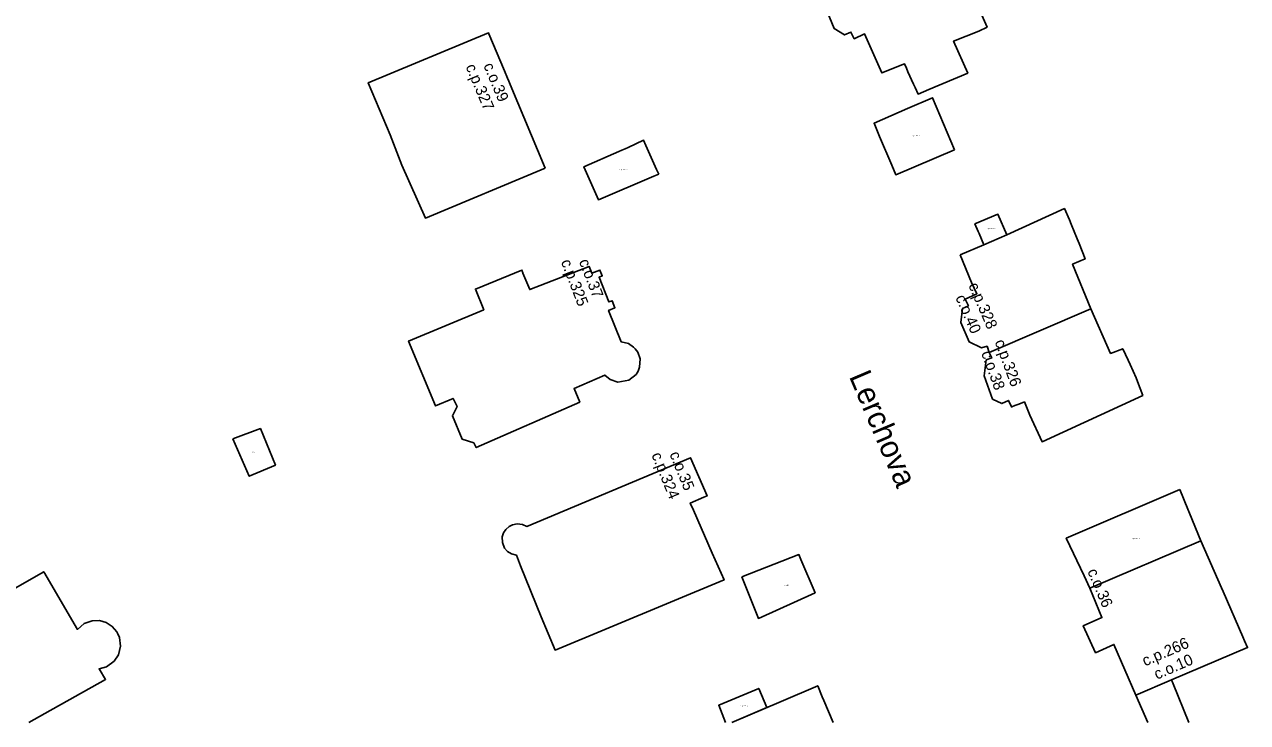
# Model space of a CAD drawing. Extents: x -600391 to -599491, y -1160176 to -1159402.
# Drawn here: x -599964.8 to -599855.4, y -1160176.1 to -1160113.6 of the extents above; entities that cross this region are included whole.
import ezdxf

# ---------------------------------------------------------------- set-up
doc = ezdxf.new("R2010")
doc.units = 0
for name, color, linetype in [('Level 10', 7, 'Continuous'), ('Level 11', 7, 'Continuous'), ('Level 12', 7, 'Continuous'), ('Level 24', 7, 'Continuous'), ('Level 25', 7, 'Continuous'), ('Level 61', 7, 'Continuous'), ('Level 62', 7, 'Continuous')]:
    doc.layers.add(name, color=color, linetype=linetype)

msp = doc.modelspace()

# ---------------------------------------------------------------- linework, layer by layer
at = {"layer": 'Level 61'}
for p, q in [((-599864.34, -1160176.08), (-599865.41, -1160173.62)), ((-599862.05, -1160172.61), (-599860.65, -1160176.08)), ((-599902.11, -1160176.08), (-599902.72, -1160174.53)), ((-599901.54, -1160176.08), (-599897.15, -1160174.19)), ((-599898.42, -1160174.74), (-599901.54, -1160176.08)), ((-599893.32, -1160174.09), (-599892.5, -1160176.08)), ((-599963.01, -1160175.26), (-599964.44, -1160176.08))]:
    msp.add_line(p, q, dxfattribs=at)
for points in [[(-599892.41, -1160113.94), (-599893.3, -1160111.75)], [(-599879.43, -1160112.2), (-599878.72, -1160113.81)], [(-599934.08, -1160118.79), (-599923.33, -1160114.31)], [(-599923.33, -1160114.31), (-599923.29, -1160114.41)], [(-599923.29, -1160114.41), (-599921.9, -1160117.72)], [(-599891.46, -1160114.5), (-599892.41, -1160113.94)], [(-599890.89, -1160114.25), (-599891.46, -1160114.5)], [(-599890.6, -1160114.85), (-599890.89, -1160114.25)], [(-599889.67, -1160114.41), (-599890.6, -1160114.85)], [(-599888.13, -1160117.9), (-599889.67, -1160114.41)], [(-599879.44, -1160114.17), (-599881.71, -1160115.05)], [(-599878.72, -1160113.81), (-599879.44, -1160114.17)], [(-599881.71, -1160115.05), (-599880.45, -1160117.92)], [(-599921.9, -1160117.72), (-599921.62, -1160118.39)], [(-599886.11, -1160117.08), (-599888.13, -1160117.9)], [(-599885.93, -1160117.49), (-599886.11, -1160117.08)], [(-599885.79, -1160117.81), (-599885.93, -1160117.49)], [(-599885.29, -1160118.9), (-599885.79, -1160117.81)], [(-599932.13, -1160123.44), (-599934.08, -1160118.79)], [(-599921.62, -1160118.39), (-599921.51, -1160118.66)], [(-599921.51, -1160118.66), (-599921.39, -1160118.94)], [(-599921.39, -1160118.94), (-599918.26, -1160126.43)], [(-599885.15, -1160119.22), (-599885.29, -1160118.9)], [(-599880.45, -1160117.92), (-599883.92, -1160119.39)], [(-599884.89, -1160119.8), (-599885.15, -1160119.22)], [(-599883.92, -1160119.39), (-599884.89, -1160119.8)], [(-599888.83, -1160122.41), (-599885.82, -1160121.1)], [(-599885.82, -1160121.1), (-599883.59, -1160120.13)], [(-599883.59, -1160120.13), (-599881.62, -1160124.79)], [(-599888.33, -1160123.61), (-599888.83, -1160122.41)], [(-599931.07, -1160126.16), (-599932.13, -1160123.44)], [(-599910.84, -1160124.59), (-599909.45, -1160123.93)], [(-599909.45, -1160123.93), (-599909.24, -1160124.4)], [(-599909.24, -1160124.4), (-599908.29, -1160126.56)], [(-599887.25, -1160126.17), (-599888.33, -1160123.61)], [(-599914.79, -1160126.31), (-599911.66, -1160124.94)], [(-599911.66, -1160124.94), (-599911.39, -1160124.82)], [(-599911.39, -1160124.82), (-599911.11, -1160124.71)], [(-599911.11, -1160124.71), (-599910.84, -1160124.59)], [(-599881.62, -1160124.79), (-599886.89, -1160127.03)], [(-599928.97, -1160130.9), (-599931.07, -1160126.16)], [(-599918.26, -1160126.43), (-599928.97, -1160130.9)], [(-599913.49, -1160129.26), (-599914.79, -1160126.31)], [(-599908.29, -1160126.56), (-599908.09, -1160126.97)], [(-599886.89, -1160127.03), (-599887.25, -1160126.17)], [(-599908.54, -1160127.16), (-599913.49, -1160129.26)], [(-599908.09, -1160126.97), (-599908.54, -1160127.16)], [(-599879.8, -1160131.43), (-599877.74, -1160130.56)], [(-599877.74, -1160130.56), (-599876.95, -1160132.42)], [(-599876.95, -1160132.42), (-599871.8, -1160130.05)], [(-599871.8, -1160130.05), (-599871.35, -1160131.07)], [(-599879.51, -1160132.11), (-599879.8, -1160131.43)], [(-599871.35, -1160131.07), (-599871.2, -1160131.45)], [(-599871.2, -1160131.45), (-599870.65, -1160132.77)], [(-599879.43, -1160132.3), (-599879.51, -1160132.11)], [(-599879.01, -1160133.3), (-599879.43, -1160132.3)], [(-599879.01, -1160133.3), (-599876.95, -1160132.42)], [(-599876.95, -1160132.42), (-599879.01, -1160133.3)], [(-599870.65, -1160132.77), (-599870.46, -1160133.19)], [(-599881.13, -1160134.21), (-599879.01, -1160133.3)], [(-599880.11, -1160136.67), (-599881.13, -1160134.21)], [(-599870.46, -1160133.19), (-599869.94, -1160134.56)], [(-599919.64, -1160137.31), (-599914.33, -1160135.23)], [(-599914.33, -1160135.23), (-599914.09, -1160135.85)], [(-599869.94, -1160134.56), (-599871.06, -1160135.04)], [(-599871.06, -1160135.04), (-599869.44, -1160139.03)], [(-599924.49, -1160137.27), (-599920.33, -1160135.56)], [(-599920.33, -1160135.56), (-599920.24, -1160135.82)], [(-599920.24, -1160135.82), (-599920.24, -1160135.83)], [(-599920.24, -1160135.83), (-599919.64, -1160137.31)], [(-599914.09, -1160135.85), (-599913.36, -1160135.56)], [(-599913.15, -1160136.09), (-599913.43, -1160136.21)], [(-599913.43, -1160136.21), (-599912.55, -1160138.42)], [(-599913.36, -1160135.56), (-599913.22, -1160135.92)], [(-599913.22, -1160135.92), (-599913.15, -1160136.09)], [(-599923.75, -1160139.12), (-599924.49, -1160137.27)], [(-599879.62, -1160137.68), (-599880.11, -1160136.67)], [(-599912.55, -1160138.42), (-599912.27, -1160138.31)], [(-599912.27, -1160138.31), (-599912.02, -1160138.94)], [(-599880.68, -1160138.16), (-599879.62, -1160137.68)], [(-599880.38, -1160138.76), (-599880.68, -1160138.16)], [(-599930.48, -1160141.92), (-599923.75, -1160139.12)], [(-599912.02, -1160138.94), (-599912.58, -1160139.17)], [(-599912.58, -1160139.17), (-599911.44, -1160141.99)], [(-599881.07, -1160140.26), (-599880.91, -1160139)], [(-599880.91, -1160139), (-599880.38, -1160138.76)], [(-599869.44, -1160139.03), (-599878.52, -1160142.95)], [(-599878.52, -1160142.95), (-599869.44, -1160139.03)], [(-599869.44, -1160139.03), (-599867.67, -1160143.03)], [(-599880.31, -1160141.99), (-599881.07, -1160140.26)], [(-599928.07, -1160147.73), (-599930.48, -1160141.92)], [(-599911.44, -1160141.99), (-599910.81, -1160142.14)], [(-599910.81, -1160142.14), (-599910.34, -1160142.45)], [(-599910.34, -1160142.45), (-599910.21, -1160142.61)], [(-599910.21, -1160142.61), (-599909.97, -1160142.91)], [(-599909.97, -1160142.91), (-599909.76, -1160143.5)], [(-599879.22, -1160142.53), (-599880.31, -1160141.99)], [(-599878.72, -1160142.38), (-599879.22, -1160142.53)], [(-599878.52, -1160142.95), (-599878.72, -1160142.38)], [(-599878.29, -1160143.42), (-599878.52, -1160142.95)], [(-599867.67, -1160143.03), (-599866.57, -1160142.6)], [(-599866.57, -1160142.6), (-599866.1, -1160143.63)], [(-599909.76, -1160143.5), (-599909.8, -1160144.26)], [(-599878.98, -1160145.04), (-599878.79, -1160143.6)], [(-599878.79, -1160143.6), (-599878.29, -1160143.42)], [(-599866.1, -1160143.63), (-599865.91, -1160144.02)], [(-599865.91, -1160144.02), (-599865.37, -1160145.2)], [(-599912.92, -1160144.97), (-599915.67, -1160146.16)], [(-599912.44, -1160145.37), (-599912.92, -1160144.97)], [(-599910.11, -1160144.9), (-599910.78, -1160145.43)], [(-599909.93, -1160144.6), (-599910.11, -1160144.9)], [(-599909.8, -1160144.26), (-599909.93, -1160144.6)], [(-599878.22, -1160147.11), (-599878.98, -1160145.04)], [(-599865.37, -1160145.2), (-599865.26, -1160145.55)], [(-599915.67, -1160146.16), (-599915.16, -1160147.38)], [(-599911.75, -1160145.59), (-599912.44, -1160145.37)], [(-599910.78, -1160145.43), (-599911.75, -1160145.59)], [(-599865.26, -1160145.55), (-599864.78, -1160146.78)], [(-599926.5, -1160147.06), (-599928.07, -1160147.73)], [(-599926.14, -1160147.79), (-599926.5, -1160147.06)], [(-599915.16, -1160147.38), (-599924.42, -1160151.46)], [(-599877.4, -1160147.51), (-599878.22, -1160147.11)], [(-599876.81, -1160147.23), (-599877.4, -1160147.51)], [(-599876.55, -1160147.76), (-599876.81, -1160147.23)], [(-599875.38, -1160147.37), (-599875.71, -1160147.5)], [(-599874.88, -1160148.56), (-599875.38, -1160147.37)], [(-599864.78, -1160146.78), (-599873.8, -1160150.94)], [(-599926.55, -1160148.61), (-599926.14, -1160147.79)], [(-599876.53, -1160147.81), (-599876.55, -1160147.76)], [(-599876.5, -1160147.8), (-599876.53, -1160147.81)], [(-599876.23, -1160147.7), (-599876.5, -1160147.8)], [(-599875.97, -1160147.6), (-599876.23, -1160147.7)], [(-599875.71, -1160147.5), (-599875.97, -1160147.6)], [(-599925.69, -1160150.71), (-599926.55, -1160148.61)], [(-599873.8, -1160150.94), (-599874.88, -1160148.56)], [(-599946.2, -1160150.66), (-599943.73, -1160149.75)], [(-599944.73, -1160154.03), (-599946.2, -1160150.66)], [(-599943.73, -1160149.75), (-599942.39, -1160153.02)], [(-599924.65, -1160151.02), (-599925.69, -1160150.71)], [(-599924.42, -1160151.46), (-599924.65, -1160151.02)], [(-599919.9, -1160158.52), (-599905.24, -1160152.37)], [(-599905.24, -1160152.37), (-599903.77, -1160155.79)], [(-599942.39, -1160153.02), (-599944.73, -1160154.03)], [(-599904.06, -1160155.91), (-599905.27, -1160156.43)], [(-599903.77, -1160155.79), (-599904.06, -1160155.91)], [(-599871.43, -1160159.47), (-599861.48, -1160155.2)], [(-599861.48, -1160155.2), (-599860.76, -1160156.96)], [(-599905.27, -1160156.43), (-599904.99, -1160157.06)], [(-599904.99, -1160157.06), (-599903.3, -1160160.9)], [(-599860.76, -1160156.96), (-599860.61, -1160157.32)], [(-599921.17, -1160158.36), (-599920.75, -1160158.28)], [(-599920.75, -1160158.28), (-599920.28, -1160158.33)], [(-599920.28, -1160158.33), (-599919.9, -1160158.52)], [(-599860.61, -1160157.32), (-599859.59, -1160159.8)], [(-599922.09, -1160159.45), (-599921.97, -1160159.09)], [(-599922.08, -1160159.95), (-599922.09, -1160159.45)], [(-599921.97, -1160159.09), (-599921.77, -1160158.78)], [(-599921.77, -1160158.78), (-599921.48, -1160158.51)], [(-599921.48, -1160158.51), (-599921.17, -1160158.36)], [(-599921.88, -1160160.45), (-599922.08, -1160159.95)], [(-599921.61, -1160160.75), (-599921.88, -1160160.45)], [(-599871.63, -1160159.57), (-599871.43, -1160159.47)], [(-599870.03, -1160162.95), (-599871.63, -1160159.57)], [(-599869.51, -1160164.05), (-599859.59, -1160159.8)], [(-599859.59, -1160159.8), (-599869.51, -1160164.05)], [(-599859.59, -1160159.8), (-599857.74, -1160164.02)], [(-599921.26, -1160160.97), (-599921.61, -1160160.75)], [(-599920.83, -1160161.09), (-599921.26, -1160160.97)], [(-599920.46, -1160162.04), (-599920.83, -1160161.09)], [(-599903.3, -1160160.9), (-599902.24, -1160163.3)], [(-599900.66, -1160163.02), (-599895.55, -1160161.04)], [(-599895.55, -1160161.04), (-599895.37, -1160161.48)], [(-599895.37, -1160161.48), (-599894.11, -1160164.45)], [(-599969.32, -1160166.11), (-599963.11, -1160162.57)], [(-599963.11, -1160162.57), (-599960.11, -1160167.74)], [(-599918.6, -1160166.62), (-599920.46, -1160162.04)], [(-599902.24, -1160163.3), (-599917.36, -1160169.59)], [(-599899.18, -1160166.76), (-599900.66, -1160163.02)], [(-599869.51, -1160164.05), (-599870.03, -1160162.95)], [(-599894.11, -1160164.45), (-599899.18, -1160166.76)], [(-599868.44, -1160166.68), (-599869.51, -1160164.05)], [(-599857.74, -1160164.02), (-599857.6, -1160164.34)], [(-599857.6, -1160164.34), (-599855.82, -1160168.41)], [(-599959.49, -1160167.22), (-599958.79, -1160166.96)], [(-599958.79, -1160166.96), (-599958.13, -1160166.95)], [(-599958.13, -1160166.95), (-599957.52, -1160167.11)], [(-599957.52, -1160167.11), (-599956.99, -1160167.47)], [(-599917.36, -1160169.59), (-599918.6, -1160166.62)], [(-599870.11, -1160167.41), (-599868.44, -1160166.68)], [(-599960.11, -1160167.74), (-599959.49, -1160167.22)], [(-599956.99, -1160167.47), (-599956.57, -1160167.95)], [(-599956.57, -1160167.95), (-599956.51, -1160168.06)], [(-599956.51, -1160168.06), (-599956.33, -1160168.46)], [(-599869.01, -1160169.83), (-599870.11, -1160167.41)], [(-599956.24, -1160169.24), (-599956.43, -1160170)], [(-599956.33, -1160168.46), (-599956.24, -1160169.24)], [(-599867.37, -1160169.08), (-599869.01, -1160169.83)], [(-599865.41, -1160173.62), (-599867.37, -1160169.08)], [(-599855.82, -1160168.41), (-599855.68, -1160168.75)], [(-599855.68, -1160168.75), (-599855.41, -1160169.36)], [(-599956.43, -1160170), (-599956.83, -1160170.59)], [(-599855.41, -1160169.36), (-599862.2, -1160172.25)], [(-599957.51, -1160171.09), (-599958.17, -1160171.27)], [(-599958.17, -1160171.27), (-599957.58, -1160172.21)], [(-599956.83, -1160170.59), (-599957.51, -1160171.09)], [(-599957.58, -1160172.21), (-599963.01, -1160175.26)], [(-599862.2, -1160172.25), (-599865.41, -1160173.62)], [(-599865.41, -1160173.62), (-599862.2, -1160172.25)], [(-599862.2, -1160172.25), (-599862.05, -1160172.61)], [(-599902.72, -1160174.53), (-599899.15, -1160173.02)], [(-599899.15, -1160173.02), (-599898.42, -1160174.74)], [(-599897.15, -1160174.19), (-599893.87, -1160172.78)], [(-599893.87, -1160172.78), (-599893.46, -1160173.77)], [(-599893.46, -1160173.77), (-599893.32, -1160174.09)]]:
    msp.add_lwpolyline(points, dxfattribs=at)
at = {"layer": 'Level 62'}
for points in [[(-599879.43, -1160112.2), (-599878.72, -1160113.81), (-599879.44, -1160114.17), (-599881.71, -1160115.05), (-599880.45, -1160117.92), (-599883.92, -1160119.39), (-599884.89, -1160119.8), (-599885.15, -1160119.22), (-599885.29, -1160118.9), (-599885.79, -1160117.81), (-599885.93, -1160117.49), (-599886.11, -1160117.08), (-599888.13, -1160117.9), (-599889.67, -1160114.41), (-599890.6, -1160114.85), (-599890.89, -1160114.25), (-599891.46, -1160114.5), (-599892.41, -1160113.94), (-599893.3, -1160111.75)], [(-599918.26, -1160126.43), (-599928.97, -1160130.9), (-599931.07, -1160126.16), (-599932.13, -1160123.44), (-599934.08, -1160118.79), (-599923.33, -1160114.31), (-599923.29, -1160114.41), (-599921.9, -1160117.72), (-599921.62, -1160118.39), (-599921.51, -1160118.66), (-599921.39, -1160118.94), (-599918.26, -1160126.43)], [(-599881.62, -1160124.79), (-599886.89, -1160127.03), (-599887.25, -1160126.17), (-599888.33, -1160123.61), (-599888.83, -1160122.41), (-599885.82, -1160121.1), (-599883.59, -1160120.13), (-599881.62, -1160124.79)], [(-599908.09, -1160126.97), (-599908.54, -1160127.16), (-599913.49, -1160129.26), (-599914.79, -1160126.31), (-599911.66, -1160124.94), (-599911.39, -1160124.82), (-599911.11, -1160124.71), (-599910.84, -1160124.59), (-599909.45, -1160123.93), (-599909.24, -1160124.4), (-599908.29, -1160126.56), (-599908.09, -1160126.97)], [(-599881.13, -1160134.21), (-599879.01, -1160133.3), (-599876.95, -1160132.42), (-599871.8, -1160130.05), (-599871.35, -1160131.07), (-599871.2, -1160131.45), (-599870.65, -1160132.77), (-599870.46, -1160133.19), (-599869.94, -1160134.56), (-599871.06, -1160135.04), (-599869.44, -1160139.03), (-599878.52, -1160142.95), (-599878.72, -1160142.38), (-599879.22, -1160142.53), (-599880.31, -1160141.99), (-599881.07, -1160140.26), (-599880.91, -1160139), (-599880.38, -1160138.76), (-599880.68, -1160138.16), (-599879.62, -1160137.68), (-599880.11, -1160136.67), (-599881.13, -1160134.21)], [(-599879.51, -1160132.11), (-599879.8, -1160131.43), (-599877.74, -1160130.56), (-599876.95, -1160132.42), (-599879.01, -1160133.3), (-599879.43, -1160132.3), (-599879.51, -1160132.11)], [(-599913.22, -1160135.92), (-599913.15, -1160136.09), (-599913.43, -1160136.21), (-599912.55, -1160138.42), (-599912.27, -1160138.31), (-599912.02, -1160138.94), (-599912.58, -1160139.17), (-599911.44, -1160141.99), (-599910.81, -1160142.14), (-599910.34, -1160142.45), (-599910.21, -1160142.61), (-599909.97, -1160142.91), (-599909.76, -1160143.5), (-599909.8, -1160144.26), (-599909.93, -1160144.6), (-599910.11, -1160144.9), (-599910.78, -1160145.43), (-599911.75, -1160145.59), (-599912.44, -1160145.37), (-599912.92, -1160144.97), (-599915.67, -1160146.16), (-599915.16, -1160147.38), (-599924.42, -1160151.46), (-599924.65, -1160151.02), (-599925.69, -1160150.71), (-599926.55, -1160148.61), (-599926.14, -1160147.79), (-599926.5, -1160147.06), (-599928.07, -1160147.73), (-599930.48, -1160141.92), (-599923.75, -1160139.12), (-599924.49, -1160137.27), (-599920.33, -1160135.56), (-599920.24, -1160135.82), (-599920.24, -1160135.83), (-599919.64, -1160137.31), (-599914.33, -1160135.23), (-599914.09, -1160135.85), (-599913.36, -1160135.56), (-599913.22, -1160135.92)], [(-599865.26, -1160145.55), (-599864.78, -1160146.78), (-599873.8, -1160150.94), (-599874.88, -1160148.56), (-599875.38, -1160147.37), (-599875.71, -1160147.5), (-599875.97, -1160147.6), (-599876.23, -1160147.7), (-599876.5, -1160147.8), (-599876.53, -1160147.81), (-599876.55, -1160147.76), (-599876.81, -1160147.23), (-599877.4, -1160147.51), (-599878.22, -1160147.11), (-599878.98, -1160145.04), (-599878.79, -1160143.6), (-599878.29, -1160143.42), (-599878.52, -1160142.95), (-599869.44, -1160139.03), (-599867.67, -1160143.03), (-599866.57, -1160142.6), (-599866.1, -1160143.63), (-599865.91, -1160144.02), (-599865.37, -1160145.2), (-599865.26, -1160145.55)], [(-599946.2, -1160150.66), (-599943.73, -1160149.75), (-599942.39, -1160153.02), (-599944.73, -1160154.03), (-599946.2, -1160150.66)], [(-599904.99, -1160157.06), (-599903.3, -1160160.9), (-599902.24, -1160163.3), (-599917.36, -1160169.59), (-599918.6, -1160166.62), (-599920.46, -1160162.04), (-599920.83, -1160161.09), (-599921.26, -1160160.97), (-599921.61, -1160160.75), (-599921.88, -1160160.45), (-599922.08, -1160159.95), (-599922.09, -1160159.45), (-599921.97, -1160159.09), (-599921.77, -1160158.78), (-599921.48, -1160158.51), (-599921.17, -1160158.36), (-599920.75, -1160158.28), (-599920.28, -1160158.33), (-599919.9, -1160158.52), (-599905.24, -1160152.37), (-599903.77, -1160155.79), (-599904.06, -1160155.91), (-599905.27, -1160156.43), (-599904.99, -1160157.06)], [(-599861.48, -1160155.2), (-599860.76, -1160156.96), (-599860.61, -1160157.32), (-599859.59, -1160159.8), (-599869.51, -1160164.05), (-599870.03, -1160162.95), (-599871.63, -1160159.57), (-599871.43, -1160159.47), (-599861.48, -1160155.2)], [(-599857.74, -1160164.02), (-599857.6, -1160164.34), (-599855.82, -1160168.41), (-599855.68, -1160168.75), (-599855.41, -1160169.36), (-599862.2, -1160172.25), (-599865.41, -1160173.62), (-599867.37, -1160169.08), (-599869.01, -1160169.83), (-599870.11, -1160167.41), (-599868.44, -1160166.68), (-599869.51, -1160164.05), (-599859.59, -1160159.8), (-599857.74, -1160164.02)], [(-599900.66, -1160163.02), (-599895.55, -1160161.04), (-599895.37, -1160161.48), (-599894.11, -1160164.45), (-599899.18, -1160166.76), (-599900.66, -1160163.02)], [(-599972.48, -1160167.87), (-599969.32, -1160166.11), (-599963.11, -1160162.57), (-599960.11, -1160167.74), (-599959.49, -1160167.22), (-599958.79, -1160166.96), (-599958.13, -1160166.95), (-599957.52, -1160167.11), (-599956.99, -1160167.47), (-599956.57, -1160167.95), (-599956.51, -1160168.06), (-599956.33, -1160168.46), (-599956.24, -1160169.24), (-599956.43, -1160170), (-599956.83, -1160170.59), (-599957.51, -1160171.09), (-599958.17, -1160171.27), (-599957.58, -1160172.21), (-599963.01, -1160175.26), (-599964.44, -1160176.08)], [(-599864.34, -1160176.08), (-599865.41, -1160173.62), (-599862.2, -1160172.25)], [(-599862.2, -1160172.25), (-599862.05, -1160172.61), (-599860.65, -1160176.08)], [(-599902.11, -1160176.08), (-599902.72, -1160174.53), (-599899.15, -1160173.02), (-599898.42, -1160174.74), (-599901.54, -1160176.08)], [(-599901.54, -1160176.08), (-599897.15, -1160174.19), (-599893.87, -1160172.78), (-599893.46, -1160173.77), (-599893.32, -1160174.09), (-599892.5, -1160176.08)]]:
    msp.add_lwpolyline(points, dxfattribs=at)

# ---------------------------------------------------------------- texts
at = {"layer": 'Level 10'}
for s, rotation, p in [('c.o.39', 292.7419, (-599923.8, -1160117.24)), ('c.o.37', 291.1066, (-599915.25, -1160134.78)), ('c.o.40', 293.5966, (-599881.57, -1160138.02)), ('c.o.38', 290.1637, (-599879.26, -1160142.99)), ('c.o.35', 292.1355, (-599907.15, -1160152.03)), ('c.o.36', 292.942, (-599869.76, -1160162.53)), ('c.o.10', 23.404, (-599863.52, -1160172.25))]:
    msp.add_text(s, height=1, rotation=rotation, dxfattribs=at).set_placement(p)
at = {"layer": 'Level 11'}
msp.add_text('Lerchova', height=2, rotation=293.155, dxfattribs=at).set_placement((-599891.09, -1160145.08))
at = {"layer": 'Level 12'}
for s, rotation, p in [('c.p.327', 292.7419, (-599925.39, -1160117.34)), ('c.p.325', 291.1066, (-599916.86, -1160134.81)), ('c.p.328', 293.5966, (-599880.41, -1160136.93)), ('c.p.326', 290.1637, (-599878.05, -1160141.98)), ('c.p.324', 292.1355, (-599908.76, -1160152.11)), ('c.p.266', 23.404, (-599864.58, -1160171.06))]:
    msp.add_text(s, height=1, rotation=rotation, dxfattribs=at).set_placement(p)
at = {"layer": 'Level 24'}
for s, p in [('c.z.4', (-599944.46, -1160151.91)), ('c.z.294', (-599896.85, -1160163.84))]:
    msp.add_text(s, height=0.1, dxfattribs=at).set_placement(p)
at = {"layer": 'Level 25'}
for s, p in [('c.pp.330_A', (-599885.42, -1160123.57)), ('c.pp.327_A', (-599911.59, -1160126.61)), ('c.pp.328_A', (-599878.68, -1160131.88)), ('c.pp.266_A', (-599865.74, -1160159.64)), ('c.pp.323_A', (-599900.8, -1160174.64))]:
    msp.add_text(s, height=0.1, dxfattribs=at).set_placement(p)

doc.saveas('drawing.dxf')
